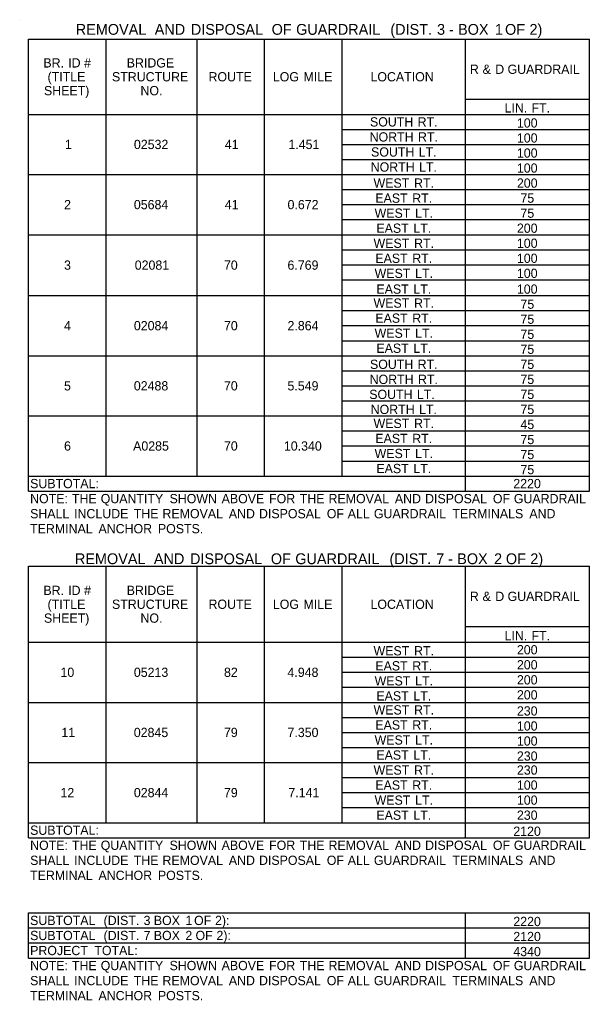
# Model space of a CAD drawing. Extents: x 544478 to 1930787, y -1948294 to 596640.
# Drawn here: x 546340 to 546709, y -1946829 to -1946194 of the extents above; entities that cross this region are included whole.
import ezdxf

# ---------------------------------------------------------------- set-up
doc = ezdxf.new("R2010")
doc.units = 0
doc.layers.add('Default', color=7, linetype='Continuous')

msp = doc.modelspace()

# ---------------------------------------------------------------- linework, layer by layer
at = {"layer": 'Default'}
for p, q in [((546339.78, -1946193.54), (546339.78, -1946193.54)), ((546345.63, -1946206.22), (546709.3, -1946206.22)), ((546345.63, -1946499.21), (546345.63, -1946206.22)), ((546345.63, -1946499.21), (546345.63, -1946206.22)), ((546395.84, -1946489.46), (546395.84, -1946206.22)), ((546454.83, -1946489.46), (546454.83, -1946206.22)), ((546498.7, -1946489.46), (546498.7, -1946206.22)), ((546548.92, -1946489.46), (546548.92, -1946206.22)), ((546628.87, -1946499.21), (546628.87, -1946206.22)), ((546709.3, -1946499.21), (546709.3, -1946206.22)), ((546709.3, -1946499.21), (546709.3, -1946206.22)), ((546628.87, -1946245.22), (546709.3, -1946245.22)), ((546345.63, -1946254.97), (546709.3, -1946254.97)), ((546345.63, -1946254.97), (546709.3, -1946254.97)), ((546548.92, -1946264.72), (546709.3, -1946264.72)), ((546548.92, -1946274.47), (546628.87, -1946274.47)), ((546548.92, -1946274.47), (546709.3, -1946274.47)), ((546548.92, -1946284.22), (546709.3, -1946284.22)), ((546345.63, -1946293.97), (546709.3, -1946293.97)), ((546548.92, -1946293.97), (546628.87, -1946293.97)), ((546628.87, -1946293.97), (546709.3, -1946293.97)), ((546548.92, -1946303.72), (546709.3, -1946303.72)), ((546548.92, -1946313.47), (546709.3, -1946313.47)), ((546548.92, -1946323.22), (546709.3, -1946323.22)), ((546345.63, -1946332.97), (546709.3, -1946332.97)), ((546548.92, -1946342.72), (546709.3, -1946342.72)), ((546548.92, -1946352.47), (546709.3, -1946352.47)), ((546548.92, -1946362.22), (546709.3, -1946362.22)), ((546345.63, -1946372.46), (546709.3, -1946372.46)), ((546548.92, -1946382.21), (546709.3, -1946382.21)), ((546548.92, -1946391.96), (546628.87, -1946391.96)), ((546548.92, -1946391.96), (546709.3, -1946391.96)), ((546548.92, -1946401.71), (546709.3, -1946401.71)), ((546345.63, -1946411.46), (546709.3, -1946411.46)), ((546548.92, -1946411.46), (546628.87, -1946411.46)), ((546628.87, -1946411.46), (546709.3, -1946411.46)), ((546548.92, -1946421.21), (546709.3, -1946421.21)), ((546548.92, -1946430.96), (546709.3, -1946430.96)), ((546548.92, -1946440.71), (546709.3, -1946440.71)), ((546345.63, -1946450.46), (546709.3, -1946450.46)), ((546548.92, -1946460.21), (546709.3, -1946460.21)), ((546548.92, -1946469.96), (546628.87, -1946469.96)), ((546548.92, -1946469.96), (546709.3, -1946469.96)), ((546548.92, -1946479.71), (546709.3, -1946479.71)), ((546345.63, -1946489.46), (546709.3, -1946489.46)), ((546548.92, -1946489.46), (546628.87, -1946489.46)), ((546628.87, -1946489.46), (546709.3, -1946489.46)), ((546628.87, -1946499.21), (546628.87, -1946489.46)), ((546345.63, -1946499.21), (546709.3, -1946499.21)), ((546345.63, -1946547.96), (546709.3, -1946547.96)), ((546345.63, -1946723.94), (546345.63, -1946547.96)), ((546345.63, -1946723.94), (546345.63, -1946547.96)), ((546395.84, -1946714.19), (546395.84, -1946547.96)), ((546454.83, -1946714.19), (546454.83, -1946547.96)), ((546498.7, -1946714.19), (546498.7, -1946547.96)), ((546548.92, -1946714.19), (546548.92, -1946547.96)), ((546628.87, -1946723.94), (546628.87, -1946547.96)), ((546709.3, -1946723.94), (546709.3, -1946547.96)), ((546709.3, -1946723.94), (546709.3, -1946547.96)), ((546628.87, -1946586.96), (546709.3, -1946586.96)), ((546345.63, -1946597.19), (546709.3, -1946597.19)), ((546628.87, -1946597.19), (546709.3, -1946597.19)), ((546548.92, -1946606.94), (546709.3, -1946606.94)), ((546548.92, -1946616.69), (546709.3, -1946616.69)), ((546548.92, -1946626.44), (546709.3, -1946626.44)), ((546345.63, -1946636.19), (546709.3, -1946636.19)), ((546548.92, -1946645.94), (546709.3, -1946645.94)), ((546548.92, -1946655.69), (546709.3, -1946655.69)), ((546548.92, -1946665.44), (546709.3, -1946665.44)), ((546345.63, -1946675.19), (546709.3, -1946675.19)), ((546548.92, -1946684.94), (546709.3, -1946684.94)), ((546548.92, -1946694.69), (546709.3, -1946694.69)), ((546548.92, -1946704.44), (546709.3, -1946704.44)), ((546345.63, -1946714.19), (546709.3, -1946714.19)), ((546345.63, -1946723.94), (546709.3, -1946723.94)), ((546345.63, -1946772.69), (546709.3, -1946772.69)), ((546345.63, -1946772.69), (546709.3, -1946772.69)), ((546345.63, -1946801.94), (546345.63, -1946772.69)), ((546345.63, -1946801.94), (546345.63, -1946772.69)), ((546628.87, -1946801.94), (546628.87, -1946772.69)), ((546628.87, -1946801.94), (546628.87, -1946772.69)), ((546709.3, -1946801.94), (546709.3, -1946772.69)), ((546709.3, -1946801.94), (546709.3, -1946772.69)), ((546345.63, -1946782.44), (546709.3, -1946782.44)), ((546345.63, -1946792.19), (546709.3, -1946792.19)), ((546345.63, -1946801.94), (546709.3, -1946801.94))]:
    msp.add_line(p, q, dxfattribs=at)

# ---------------------------------------------------------------- texts
for s, height, p in [('REMOVAL', 7, (546376.19, -1946203.38)), (' DISPOSAL', 7, (546448.23, -1946203.38)), (' OF', 7, (546500.65, -1946203.38)), (' GUARDRAIL', 7, (546516.5, -1946203.38)), (' (DIST.', 7, (546577.6, -1946203.38)), (' 3', 7, (546607.9, -1946203.38)), (' BOX', 7, (546621.53, -1946203.38)), (' OF', 7, (546652, -1946203.38)), (' 2)', 7, (546667.85, -1946203.38)), (' AND', 7, (546424.8, -1946203.38)), (' -', 7, (546615.63, -1946203.38)), (' 1', 7, (546645.43, -1946203.38)), ('BR.', 6, (546355.21, -1946224.59)), (' ID', 6, (546369.07, -1946224.59)), (' #', 6, (546379.37, -1946224.59)), ('BRIDGE', 6, (546409.24, -1946224.59)), ('(TITLE', 6, (546357.91, -1946233.59)), ('STRUCTURE', 6, (546399.69, -1946233.59)), ('ROUTE', 6, (546462.3, -1946233.59)), ('LOG', 6, (546504.01, -1946233.59)), (' MILE', 6, (546521.67, -1946233.59)), ('LOCATION', 6, (546567.34, -1946233.59)), ('R', 6, (546631.78, -1946228.72)), (' &', 6, (546637.8, -1946228.72)), (' D', 6, (546646.04, -1946228.72)), (' GUARDRAIL', 6, (546654.01, -1946228.72)), ('SHEET)', 6, (546355.58, -1946242.59)), ('NO.', 6, (546418.17, -1946242.59)), ('LIN.', 6, (546654.3, -1946253.77)), (' FT.', 6, (546669.55, -1946253.77)), ('SOUTH', 6, (546567.01, -1946262.84)), (' RT.', 6, (546595.68, -1946262.84)), ('100', 6, (546662.3, -1946263.52)), ('1', 6, (546369.18, -1946277.47)), ('02532', 6, (546413.91, -1946277.47)), ('41', 6, (546472.88, -1946277.47)), ('1.451', 6, (546514.1, -1946277.47)), ('NORTH', 6, (546566.78, -1946272.59)), (' RT.', 6, (546595.91, -1946272.59)), ('100', 6, (546662.3, -1946273.27)), ('SOUTH', 6, (546567.7, -1946282.34)), (' LT.', 6, (546596.37, -1946282.34)), ('100', 6, (546662.3, -1946283.02)), ('NORTH', 6, (546567.47, -1946292.09)), (' LT.', 6, (546596.6, -1946292.09)), ('100', 6, (546662.3, -1946292.77)), ('WEST', 6, (546569.32, -1946302.52)), (' RT.', 6, (546593.37, -1946302.52)), ('200', 6, (546662.3, -1946302.52)), ('2', 6, (546368.63, -1946316.47)), ('05684', 6, (546413.89, -1946316.47)), ('41', 6, (546472.88, -1946316.47)), ('0.672', 6, (546513.55, -1946316.47)), ('EAST', 6, (546570.48, -1946312.27)), (' RT.', 6, (546592.21, -1946312.27)), ('75', 6, (546664.59, -1946312.27)), ('WEST', 6, (546570.01, -1946322.02)), (' LT.', 6, (546594.06, -1946322.02)), ('75', 6, (546664.59, -1946322.02)), ('EAST', 6, (546571.17, -1946331.77)), (' LT.', 6, (546592.91, -1946331.77)), ('200', 6, (546662.3, -1946331.77)), ('WEST', 6, (546569.32, -1946341.52)), (' RT.', 6, (546593.37, -1946341.52)), ('100', 6, (546662.3, -1946341.52)), ('EAST', 6, (546570.48, -1946351.27)), (' RT.', 6, (546592.21, -1946351.27)), ('100', 6, (546662.3, -1946351.27)), ('3', 6, (546368.6, -1946355.71)), ('02081', 6, (546414.46, -1946355.71)), ('70', 6, (546472.31, -1946355.71)), ('6.769', 6, (546513.51, -1946355.71)), ('WEST', 6, (546570.01, -1946361.02)), (' LT.', 6, (546594.06, -1946361.02)), ('100', 6, (546662.3, -1946361.02)), ('EAST', 6, (546571.17, -1946371.26)), (' LT.', 6, (546592.91, -1946371.26)), ('100', 6, (546662.3, -1946371.26)), ('WEST', 6, (546569.32, -1946380.33)), (' RT.', 6, (546593.37, -1946380.33)), ('75', 6, (546664.59, -1946381.01)), ('EAST', 6, (546570.48, -1946390.08)), (' RT.', 6, (546592.21, -1946390.08)), ('75', 6, (546664.59, -1946390.76)), ('4', 6, (546368.61, -1946394.96)), ('02084', 6, (546413.89, -1946394.96)), ('70', 6, (546472.31, -1946394.96)), ('2.864', 6, (546513.53, -1946394.96)), ('WEST', 6, (546570.01, -1946399.83)), (' LT.', 6, (546594.06, -1946399.83)), ('75', 6, (546664.59, -1946400.51)), ('EAST', 6, (546571.17, -1946409.58)), (' LT.', 6, (546592.91, -1946409.58)), ('75', 6, (546664.59, -1946410.26)), ('SOUTH', 6, (546567.01, -1946420.01)), (' RT.', 6, (546595.68, -1946420.01)), ('75', 6, (546664.59, -1946420.01)), ('NORTH', 6, (546566.78, -1946429.76)), (' RT.', 6, (546595.91, -1946429.76)), ('75', 6, (546664.59, -1946429.76)), ('5', 6, (546368.57, -1946433.96)), ('02488', 6, (546413.87, -1946433.96)), ('70', 6, (546472.31, -1946433.96)), ('5.549', 6, (546513.51, -1946433.96)), ('SOUTH', 6, (546566.54, -1946439.51)), (' LT.', 6, (546595.21, -1946439.51)), ('75', 6, (546664.59, -1946439.51)), ('NORTH', 6, (546567.47, -1946449.26)), (' LT.', 6, (546596.6, -1946449.26)), ('75', 6, (546664.59, -1946449.26)), ('WEST', 6, (546569.32, -1946458.33)), (' RT.', 6, (546593.37, -1946458.33)), ('45', 6, (546664.59, -1946459.01)), ('EAST', 6, (546570.48, -1946468.08)), (' RT.', 6, (546592.21, -1946468.08)), ('75', 6, (546664.59, -1946468.76)), ('6', 6, (546368.6, -1946472.96)), ('A0285', 6, (546413.39, -1946472.96)), ('70', 6, (546472.31, -1946472.96)), ('10.340', 6, (546511.2, -1946472.96)), ('WEST', 6, (546570.01, -1946477.83)), (' LT.', 6, (546594.06, -1946477.83)), ('75', 6, (546664.59, -1946478.51)), ('EAST', 6, (546571.17, -1946487.58)), (' LT.', 6, (546592.91, -1946487.58)), ('75', 6, (546664.59, -1946488.26)), ('SUBTOTAL:', 6, (546346.6, -1946497.33)), ('2220', 6, (546659.97, -1946497.33)), ('NOTE:', 6, (546346.6, -1946507.08)), (' THE', 6, (546371.49, -1946507.08)), (' QUANTITY', 6, (546390.14, -1946507.08)), (' SHOWN', 6, (546434.79, -1946507.08)), (' ABOVE', 6, (546468.57, -1946507.08)), (' FOR', 6, (546499.34, -1946507.08)), (' THE', 6, (546519.26, -1946507.08)), (' REMOVAL', 6, (546537.9, -1946507.08)), (' AND', 6, (546580.93, -1946507.08)), (' DISPOSAL', 6, (546600.52, -1946507.08)), (' OF', 6, (546644.48, -1946507.08)), (' GUARDRAIL', 6, (546658.07, -1946507.08)), ('SHALL', 6, (546346.6, -1946516.83)), (' INCLUDE', 6, (546372.87, -1946516.83)), (' THE', 6, (546411.55, -1946516.83)), (' REMOVAL', 6, (546430.2, -1946516.83)), (' AND', 6, (546473.23, -1946516.83)), (' DISPOSAL', 6, (546492.81, -1946516.83)), (' OF', 6, (546536.78, -1946516.83)), (' ALL', 6, (546550.36, -1946516.83)), (' GUARDRAIL', 6, (546567.31, -1946516.83)), (' TERMINALS', 6, (546618.25, -1946516.83)), (' AND', 6, (546668.12, -1946516.83)), (' ANCHOR', 6, (546388.7, -1946526.58)), (' POSTS.', 6, (546427.24, -1946526.58)), ('TERMINAL', 6, (546346.6, -1946526.58)), ('REMOVAL', 7, (546375.65, -1946546.58)), (' AND', 7, (546424.26, -1946546.58)), (' DISPOSAL', 7, (546447.68, -1946546.58)), (' OF', 7, (546500.11, -1946546.58)), (' GUARDRAIL', 7, (546515.96, -1946546.58)), (' (DIST.', 7, (546577.06, -1946546.58)), (' 7', 7, (546607.36, -1946546.58)), (' BOX', 7, (546620.98, -1946546.58)), (' 2', 7, (546644.88, -1946546.58)), (' OF', 7, (546652.54, -1946546.58)), (' 2)', 7, (546668.39, -1946546.58)), (' -', 7, (546615.08, -1946546.58)), ('BR.', 6, (546355.21, -1946566.57)), (' ID', 6, (546369.07, -1946566.57)), (' #', 6, (546379.37, -1946566.57)), ('BRIDGE', 6, (546409.24, -1946566.57)), ('R', 6, (546631.78, -1946570.46)), (' &', 6, (546637.8, -1946570.46)), (' D', 6, (546646.04, -1946570.46)), (' GUARDRAIL', 6, (546654.01, -1946570.46)), ('(TITLE', 6, (546357.91, -1946575.57)), ('STRUCTURE', 6, (546399.69, -1946575.57)), ('ROUTE', 6, (546462.3, -1946575.57)), ('LOG', 6, (546504.01, -1946575.57)), (' MILE', 6, (546521.67, -1946575.57)), ('LOCATION', 6, (546567.34, -1946575.57)), ('SHEET)', 6, (546355.58, -1946584.57)), ('NO.', 6, (546418.17, -1946584.57)), ('LIN.', 6, (546654.3, -1946595.99)), (' FT.', 6, (546669.55, -1946595.99)), ('WEST', 6, (546569.32, -1946605.74)), (' RT.', 6, (546593.37, -1946605.74)), ('200', 6, (546662.3, -1946605.07)), ('EAST', 6, (546570.48, -1946615.49)), (' RT.', 6, (546592.21, -1946615.49)), ('200', 6, (546662.3, -1946614.82)), ('10', 6, (546366.28, -1946619.69)), ('05213', 6, (546413.88, -1946619.69)), ('82', 6, (546472.33, -1946619.69)), ('4.948', 6, (546513.51, -1946619.69)), ('WEST', 6, (546570.01, -1946625.24)), (' LT.', 6, (546594.06, -1946625.24)), ('200', 6, (546662.3, -1946624.57)), ('200', 6, (546662.3, -1946634.32)), ('EAST', 6, (546571.17, -1946634.99)), (' LT.', 6, (546592.91, -1946634.99)), ('WEST', 6, (546569.32, -1946644.07)), (' RT.', 6, (546593.37, -1946644.07)), ('230', 6, (546662.3, -1946644.74)), ('EAST', 6, (546570.48, -1946653.82)), ('11', 6, (546366.85, -1946658.69)), ('02845', 6, (546413.85, -1946658.69)), ('79', 6, (546472.29, -1946658.69)), ('7.350', 6, (546513.53, -1946658.69)), (' RT.', 6, (546592.21, -1946653.82)), ('100', 6, (546662.3, -1946654.49)), ('WEST', 6, (546570.01, -1946663.57)), (' LT.', 6, (546594.06, -1946663.57)), ('100', 6, (546662.3, -1946664.24)), ('EAST', 6, (546571.17, -1946673.32)), (' LT.', 6, (546592.91, -1946673.32)), ('230', 6, (546662.3, -1946673.99)), ('WEST', 6, (546569.32, -1946683.07)), (' RT.', 6, (546593.37, -1946683.07)), ('230', 6, (546662.3, -1946683.07)), ('12', 6, (546366.3, -1946697.69)), ('02844', 6, (546413.89, -1946697.69)), ('79', 6, (546472.29, -1946697.69)), ('7.141', 6, (546514.1, -1946697.69)), ('EAST', 6, (546570.48, -1946692.82)), (' RT.', 6, (546592.21, -1946692.82)), ('100', 6, (546662.3, -1946692.82)), ('WEST', 6, (546570.01, -1946702.57)), (' LT.', 6, (546594.06, -1946702.57)), ('100', 6, (546662.3, -1946702.57)), ('EAST', 6, (546571.17, -1946712.32)), (' LT.', 6, (546592.91, -1946712.32)), ('230', 6, (546662.3, -1946712.32)), ('SUBTOTAL:', 6, (546346.6, -1946722.07)), ('2120', 6, (546659.97, -1946722.74)), ('NOTE:', 6, (546346.6, -1946731.82)), (' THE', 6, (546371.49, -1946731.82)), (' QUANTITY', 6, (546390.14, -1946731.82)), (' SHOWN', 6, (546434.79, -1946731.82)), (' ABOVE', 6, (546468.57, -1946731.82)), (' FOR', 6, (546499.34, -1946731.82)), (' THE', 6, (546519.26, -1946731.82)), (' REMOVAL', 6, (546537.9, -1946731.82)), (' AND', 6, (546580.93, -1946731.82)), (' DISPOSAL', 6, (546600.52, -1946731.82)), (' OF', 6, (546644.48, -1946731.82)), (' GUARDRAIL', 6, (546658.07, -1946731.82)), ('SHALL', 6, (546346.6, -1946741.57)), (' INCLUDE', 6, (546372.87, -1946741.57)), (' THE', 6, (546411.55, -1946741.57)), (' REMOVAL', 6, (546430.2, -1946741.57)), (' AND', 6, (546473.23, -1946741.57)), (' DISPOSAL', 6, (546492.81, -1946741.57)), (' OF', 6, (546536.78, -1946741.57)), (' ALL', 6, (546550.36, -1946741.57)), (' GUARDRAIL', 6, (546567.31, -1946741.57)), (' TERMINALS', 6, (546618.25, -1946741.57)), (' AND', 6, (546668.12, -1946741.57)), ('TERMINAL', 6, (546346.6, -1946751.32)), (' ANCHOR', 6, (546388.7, -1946751.32)), (' POSTS.', 6, (546427.24, -1946751.32)), ('SUBTOTAL', 6, (546346.6, -1946780.57)), (' (DIST.', 6, (546392, -1946780.57)), (' 3', 6, (546417.96, -1946780.57)), (' BOX', 6, (546424.59, -1946780.57)), (' 1', 6, (546445.08, -1946780.57)), (' OF', 6, (546450.71, -1946780.57)), (' 2):', 6, (546464.29, -1946780.57)), ('2220', 6, (546659.97, -1946781.24)), ('SUBTOTAL', 6, (546346.6, -1946790.32)), (' (DIST.', 6, (546392, -1946790.32)), (' 7', 6, (546417.96, -1946790.32)), (' BOX', 6, (546424.58, -1946790.32)), (' 2', 6, (546445.07, -1946790.32)), (' OF', 6, (546451.64, -1946790.32)), (' 2):', 6, (546465.22, -1946790.32)), ('2120', 6, (546659.97, -1946790.99)), ('PROJECT', 6, (546346.6, -1946800.07)), (' TOTAL:', 6, (546386.03, -1946800.07)), ('4340', 6, (546659.97, -1946800.74)), ('NOTE:', 6, (546346.6, -1946809.82)), (' THE', 6, (546371.49, -1946809.82)), (' QUANTITY', 6, (546390.14, -1946809.82)), (' SHOWN', 6, (546434.79, -1946809.82)), (' ABOVE', 6, (546468.57, -1946809.82)), (' FOR', 6, (546499.34, -1946809.82)), (' THE', 6, (546519.26, -1946809.82)), (' REMOVAL', 6, (546537.9, -1946809.82)), (' AND', 6, (546580.93, -1946809.82)), (' DISPOSAL', 6, (546600.52, -1946809.82)), (' OF', 6, (546644.48, -1946809.82)), (' GUARDRAIL', 6, (546658.07, -1946809.82)), ('SHALL', 6, (546346.6, -1946819.57)), (' INCLUDE', 6, (546372.87, -1946819.57)), (' THE', 6, (546411.55, -1946819.57)), (' REMOVAL', 6, (546430.2, -1946819.57)), (' AND', 6, (546473.23, -1946819.57)), (' DISPOSAL', 6, (546492.81, -1946819.57)), (' OF', 6, (546536.78, -1946819.57)), (' ALL', 6, (546550.36, -1946819.57)), (' GUARDRAIL', 6, (546567.31, -1946819.57)), (' TERMINALS', 6, (546618.25, -1946819.57)), (' AND', 6, (546668.12, -1946819.57)), ('TERMINAL', 6, (546346.6, -1946829.32)), (' ANCHOR', 6, (546388.7, -1946829.32)), (' POSTS.', 6, (546427.24, -1946829.32))]:
    msp.add_text(s, height=height, dxfattribs=at).set_placement(p)

doc.saveas('drawing.dxf')
